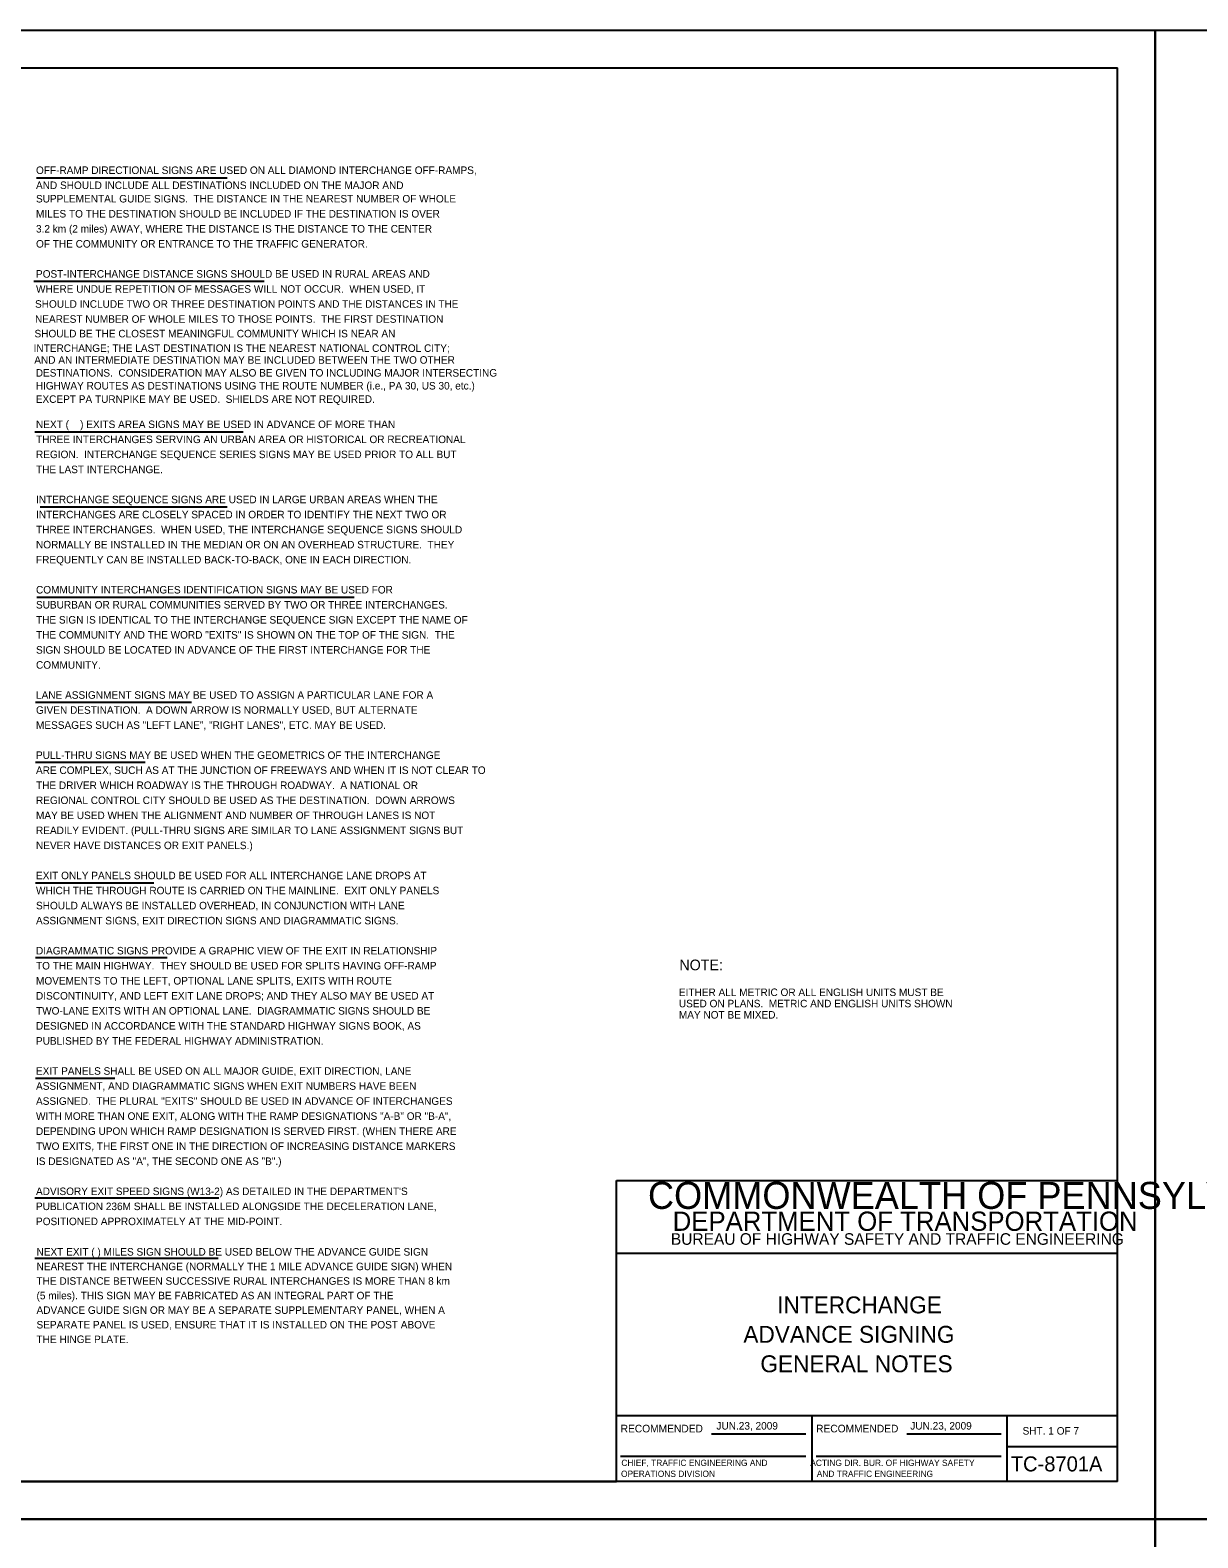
# Model space of a CAD drawing. Extents: x 640994 to 644422, y 298458 to 299646.
# Drawn here: x 641386 to 641852, y 299044 to 299646 of the extents above; entities that cross this region are included whole.
import ezdxf

# ---------------------------------------------------------------- set-up
doc = ezdxf.new("R2010")
doc.units = 0
for name, color, linetype in [('1', 7, 'Continuous'), ('2', 7, 'Continuous'), ('PLT-BNDY', 7, 'Continuous'), ('XCS-GRID-MIN', 7, 'Continuous')]:
    doc.layers.add(name, color=color, linetype=linetype)

msp = doc.modelspace()

# ---------------------------------------------------------------- linework, layer by layer
at = {"layer": '1'}
for p, q in [((641034.31, 299630.63), (641820.31, 299630.63)), ((641820.31, 299066.63), (641820.31, 299630.63)), ((641620.31, 299066.63), (641620.31, 299186.63)), ((641620.31, 299186.63), (641820.31, 299186.63)), ((641820.31, 299157.63), (641620.31, 299157.63)), ((641620.31, 299093), (641820.31, 299093)), ((641698.31, 299093), (641698.31, 299066.63)), ((641776.19, 299066.63), (641776.19, 299093)), ((641658.24, 299085.57), (641695.87, 299085.57)), ((641736.24, 299085.57), (641773.87, 299085.57)), ((641776.19, 299080.63), (641820.31, 299080.63)), ((641621.99, 299076.68), (641695.87, 299076.68)), ((641699.99, 299076.68), (641773.87, 299076.68)), ((641820.31, 299066.63), (641034.31, 299066.63)), ((641034.31, 299066.63), (641620.31, 299066.63))]:
    msp.add_line(p, q, dxfattribs=at)
at = {"layer": '2'}
for p, q in [((641388.94, 299586.75), (641464.94, 299586.75)), ((641387.81, 299545.5), (641479.69, 299545.5)), ((641388.19, 299485.38), (641471.31, 299485.38)), ((641390.31, 299455.5), (641464.94, 299455.5)), ((641389.06, 299419.38), (641515.69, 299419.38)), ((641388.44, 299377.5), (641450.69, 299377.5)), ((641388.44, 299353.63), (641432.31, 299353.63)), ((641388.44, 299305.5), (641435.69, 299305.5)), ((641388.44, 299275.63), (641441.06, 299275.63)), ((641388.44, 299227.5), (641420.19, 299227.5)), ((641388.19, 299179.75), (641461.69, 299179.75)), ((641388.19, 299155.75), (641461.32, 299155.75))]:
    msp.add_line(p, q, dxfattribs=at)
at = {"layer": 'XCS-GRID-MIN'}
for points in [[(640994.31, 299645.63), (641835.31, 299645.63), (641835.31, 299051.63), (640994.31, 299051.63)], [(641835.31, 299645.63), (642676.31, 299645.63), (642676.31, 299051.63), (641835.31, 299051.63)], [(640994.31, 299051.63), (641835.31, 299051.63), (641835.31, 298457.63), (640994.31, 298457.63)], [(641835.31, 299051.63), (642676.31, 299051.63), (642676.31, 298457.63), (641835.31, 298457.63)]]:
    msp.add_lwpolyline(points, close=True, dxfattribs=at)

# ---------------------------------------------------------------- texts
at = {"layer": '1'}
for s, height, p in [('COMMONWEALTH OF PENNSYLVANIA', 10.7828, (641632.9, 299175.36)), ('DEPARTMENT OF TRANSPORTATION', 7.6837, (641642.76, 299166.61)), ('BUREAU OF HIGHWAY SAFETY AND TRAFFIC ENGINEERING', 4.6253, (641642.04, 299161.04)), ('INTERCHANGE', 6.75, (641684.49, 299133.69)), ('ADVANCE SIGNING', 6.75, (641670.96, 299121.94)), ('GENERAL NOTES', 6.75, (641677.74, 299110.19)), ('RECOMMENDED', 3.048, (641621.99, 299086.2)), ('RECOMMENDED', 3.048, (641699.99, 299086.2)), ('SHT. 1 OF 7', 3, (641782.4, 299085.31)), ('TC-8701A', 6, (641777.68, 299070.63))]:
    msp.add_text(s, height=height, dxfattribs=at).set_placement(p)
at = {"layer": '2'}
for s, height, p in [('OFF-RAMP DIRECTIONAL SIGNS ARE USED ON ALL DIAMOND INTERCHANGE OFF-RAMPS,', 3, (641388.69, 299588.25)), ('AND SHOULD INCLUDE ALL DESTINATIONS INCLUDED ON THE MAJOR AND', 3, (641388.69, 299582.25)), ('SUPPLEMENTAL GUIDE SIGNS.  THE DISTANCE IN THE NEAREST NUMBER OF WHOLE', 3, (641388.69, 299576.88)), ('MILES TO THE DESTINATION SHOULD BE INCLUDED IF THE DESTINATION IS OVER ', 3, (641388.69, 299570.88)), ('3.2 km (2 miles) AWAY, WHERE THE DISTANCE IS THE DISTANCE TO THE CENTER ', 3, (641388.69, 299564.88)), ('OF THE COMMUNITY OR ENTRANCE TO THE TRAFFIC GENERATOR.', 3, (641388.69, 299558.88)), ('POST-INTERCHANGE DISTANCE SIGNS SHOULD BE USED IN RURAL AREAS AND', 3, (641388.69, 299546.88)), ('WHERE UNDUE REPETITION OF MESSAGES WILL NOT OCCUR.  WHEN USED, IT', 3, (641388.69, 299540.88)), ('SHOULD INCLUDE TWO OR THREE DESTINATION POINTS AND THE DISTANCES IN THE', 3, (641388.3, 299534.88)), ('NEAREST NUMBER OF WHOLE MILES TO THOSE POINTS.  THE FIRST DESTINATION', 3, (641388.3, 299528.88)), ('SHOULD BE THE CLOSEST MEANINGFUL COMMUNITY WHICH IS NEAR AN', 3, (641388.11, 299523.07)), ('INTERCHANGE; THE LAST DESTINATION IS THE NEAREST NATIONAL CONTROL CITY;', 3, (641387.73, 299517.26)), ('AND AN INTERMEDIATE DESTINATION MAY BE INCLUDED BETWEEN THE TWO OTHER', 3, (641388.01, 299512.55)), ('DESTINATIONS.  CONSIDERATION MAY ALSO BE GIVEN TO INCLUDING MAJOR INTERSECTING', 3, (641388.59, 299507.41)), ('HIGHWAY ROUTES AS DESTINATIONS USING THE ROUTE NUMBER (i.e., PA 30, US 30, etc.)', 3, (641388.59, 299502.26)), ('EXCEPT PA TURNPIKE MAY BE USED.  SHIELDS ARE NOT REQUIRED.', 3, (641388.59, 299496.93)), ('NEXT (    ) EXITS AREA SIGNS MAY BE USED IN ADVANCE OF MORE THAN', 3, (641388.69, 299486.88)), ('THREE INTERCHANGES SERVING AN URBAN AREA OR HISTORICAL OR RECREATIONAL', 3, (641388.69, 299480.88)), ('REGION.  INTERCHANGE SEQUENCE SERIES SIGNS MAY BE USED PRIOR TO ALL BUT', 3, (641388.69, 299474.88)), ('THE LAST INTERCHANGE.', 3, (641388.69, 299468.88)), ('INTERCHANGE SEQUENCE SIGNS ARE USED IN LARGE URBAN AREAS WHEN THE', 3, (641388.69, 299456.88)), ('INTERCHANGES ARE CLOSELY SPACED IN ORDER TO IDENTIFY THE NEXT TWO OR', 3, (641388.69, 299450.88)), ('THREE INTERCHANGES.  WHEN USED, THE INTERCHANGE SEQUENCE SIGNS SHOULD', 3, (641388.69, 299444.88)), ('NORMALLY BE INSTALLED IN THE MEDIAN OR ON AN OVERHEAD STRUCTURE.  THEY', 3, (641388.69, 299438.88)), ('FREQUENTLY CAN BE INSTALLED BACK-TO-BACK, ONE IN EACH DIRECTION.', 3, (641388.69, 299432.88)), ('COMMUNITY INTERCHANGES IDENTIFICATION SIGNS MAY BE USED FOR', 3, (641388.69, 299420.88)), ('SUBURBAN OR RURAL COMMUNITIES SERVED BY TWO OR THREE INTERCHANGES. ', 3, (641388.69, 299414.88)), ('THE SIGN IS IDENTICAL TO THE INTERCHANGE SEQUENCE SIGN EXCEPT THE NAME OF', 3, (641388.69, 299408.88)), ('THE COMMUNITY AND THE WORD "EXITS" IS SHOWN ON THE TOP OF THE SIGN.  THE', 3, (641388.69, 299402.88)), ('SIGN SHOULD BE LOCATED IN ADVANCE OF THE FIRST INTERCHANGE FOR THE', 3, (641388.69, 299396.88)), ('COMMUNITY.', 3, (641388.69, 299390.88)), ('LANE ASSIGNMENT SIGNS MAY BE USED TO ASSIGN A PARTICULAR LANE FOR A', 3, (641388.69, 299378.88)), ('GIVEN DESTINATION.  A DOWN ARROW IS NORMALLY USED, BUT ALTERNATE', 3, (641388.69, 299372.88)), ('MESSAGES SUCH AS "LEFT LANE", "RIGHT LANES", ETC. MAY BE USED.', 3, (641388.69, 299366.88)), ('PULL-THRU SIGNS MAY BE USED WHEN THE GEOMETRICS OF THE INTERCHANGE', 3, (641388.69, 299354.88)), ('ARE COMPLEX, SUCH AS AT THE JUNCTION OF FREEWAYS AND WHEN IT IS NOT CLEAR TO', 3, (641388.69, 299348.88)), ('THE DRIVER WHICH ROADWAY IS THE THROUGH ROADWAY.  A NATIONAL OR', 3, (641388.69, 299342.88)), ('REGIONAL CONTROL CITY SHOULD BE USED AS THE DESTINATION.  DOWN ARROWS', 3, (641388.69, 299336.88)), ('MAY BE USED WHEN THE ALIGNMENT AND NUMBER OF THROUGH LANES IS NOT', 3, (641388.69, 299330.88)), ('READILY EVIDENT. (PULL-THRU SIGNS ARE SIMILAR TO LANE ASSIGNMENT SIGNS BUT', 3, (641388.69, 299324.88)), ('NEVER HAVE DISTANCES OR EXIT PANELS.)', 3, (641388.69, 299318.88)), ('EXIT ONLY PANELS SHOULD BE USED FOR ALL INTERCHANGE LANE DROPS AT', 3, (641388.69, 299306.88)), ('WHICH THE THROUGH ROUTE IS CARRIED ON THE MAINLINE.  EXIT ONLY PANELS', 3, (641388.69, 299300.88)), ('SHOULD ALWAYS BE INSTALLED OVERHEAD, IN CONJUNCTION WITH LANE', 3, (641388.69, 299294.88)), ('ASSIGNMENT SIGNS, EXIT DIRECTION SIGNS AND DIAGRAMMATIC SIGNS.', 3, (641388.69, 299288.88)), ('DIAGRAMMATIC SIGNS PROVIDE A GRAPHIC VIEW OF THE EXIT IN RELATIONSHIP', 3, (641388.69, 299276.88)), ('TO THE MAIN HIGHWAY.  THEY SHOULD BE USED FOR SPLITS HAVING OFF-RAMP', 3, (641388.69, 299270.88)), ('NOTE:', 4.25, (641645.44, 299270.57)), ('MOVEMENTS TO THE LEFT, OPTIONAL LANE SPLITS, EXITS WITH ROUTE', 3, (641388.69, 299264.88)), ('DISCONTINUITY, AND LEFT EXIT LANE DROPS; AND THEY ALSO MAY BE USED AT', 3, (641388.69, 299258.88)), ('USED ON PLANS.  METRIC AND ENGLISH UNITS SHOWN', 3, (641645.23, 299255.79)), ('EITHER ALL METRIC OR ALL ENGLISH UNITS MUST BE', 3, (641645.23, 299260.29)), ('TWO-LANE EXITS WITH AN OPTIONAL LANE.  DIAGRAMMATIC SIGNS SHOULD BE', 3, (641388.69, 299252.88)), ('MAY NOT BE MIXED.', 3, (641645.23, 299251.29)), ('DESIGNED IN ACCORDANCE WITH THE STANDARD HIGHWAY SIGNS BOOK, AS', 3, (641388.69, 299246.88)), ('PUBLISHED BY THE FEDERAL HIGHWAY ADMINISTRATION.', 3, (641388.69, 299240.88)), ('EXIT PANELS SHALL BE USED ON ALL MAJOR GUIDE, EXIT DIRECTION, LANE', 3, (641388.69, 299228.88)), ('ASSIGNMENT, AND DIAGRAMMATIC SIGNS WHEN EXIT NUMBERS HAVE BEEN', 3, (641388.69, 299222.88)), ('ASSIGNED.  THE PLURAL "EXITS" SHOULD BE USED IN ADVANCE OF INTERCHANGES', 3, (641388.69, 299216.88)), ('WITH MORE THAN ONE EXIT, ALONG WITH THE RAMP DESIGNATIONS "A-B" OR "B-A",', 3, (641388.69, 299210.88)), ('DEPENDING UPON WHICH RAMP DESIGNATION IS SERVED FIRST. (WHEN THERE ARE', 3, (641388.69, 299204.88)), ('TWO EXITS, THE FIRST ONE IN THE DIRECTION OF INCREASING DISTANCE MARKERS', 3, (641388.69, 299198.88)), ('IS DESIGNATED AS "A", THE SECOND ONE AS "B".)', 3, (641388.69, 299192.88)), ("ADVISORY EXIT SPEED SIGNS (W13-2) AS DETAILED IN THE DEPARTMENT'S", 3, (641388.69, 299180.88)), ('PUBLICATION 236M SHALL BE INSTALLED ALONGSIDE THE DECELERATION LANE,', 3, (641388.69, 299174.88)), ('POSITIONED APPROXIMATELY AT THE MID-POINT.', 3, (641388.69, 299168.88)), ('NEXT EXIT ( ) MILES SIGN SHOULD BE USED BELOW THE ADVANCE GUIDE SIGN', 3, (641388.9, 299156.73)), ('NEAREST THE INTERCHANGE (NORMALLY THE 1 MILE ADVANCE GUIDE SIGN) WHEN', 3, (641388.9, 299150.91)), ('THE DISTANCE BETWEEN SUCCESSIVE RURAL INTERCHANGES IS MORE THAN 8 km', 3, (641388.9, 299145.1)), ('(5 miles). THIS SIGN MAY BE FABRICATED AS AN INTEGRAL PART OF THE ', 3, (641388.9, 299139.29)), ('ADVANCE GUIDE SIGN OR MAY BE A SEPARATE SUPPLEMENTARY PANEL, WHEN A ', 3, (641388.9, 299133.48)), ('SEPARATE PANEL IS USED, ENSURE THAT IT IS INSTALLED ON THE POST ABOVE ', 3, (641388.9, 299127.66)), ('THE HINGE PLATE.', 3, (641388.9, 299121.85)), ('JUN.23, 2009', 3, (641660.22, 299087.32))]:
    msp.add_text(s, height=height, dxfattribs=at).set_placement(p)
msp.add_text('JUN.23, 2009', height=3, rotation=360, dxfattribs=at).set_placement((641737.58, 299087.32))
at = {"layer": 'PLT-BNDY'}
for s, p in [('CHIEF, TRAFFIC ENGINEERING AND', (641622.28, 299072.81)), ('  ACTING DIR. BUR. OF HIGHWAY SAFETY', (641695.81, 299072.8)), ('  ACTING DIR. BUR. OF HIGHWAY SAFETY', (641695.81, 299072.8)), ('OPERATIONS DIVISION', (641622.14, 299068.44))]:
    msp.add_text(s, height=2.5, dxfattribs=at).set_placement(p)
msp.add_text('AND TRAFFIC ENGINEERING', height=2.5, rotation=360, dxfattribs=at).set_placement((641700.25, 299068.43))
msp.add_text('AND TRAFFIC ENGINEERING', height=2.5, rotation=360, dxfattribs=at).set_placement((641700.25, 299068.43))

doc.saveas('drawing.dxf')
